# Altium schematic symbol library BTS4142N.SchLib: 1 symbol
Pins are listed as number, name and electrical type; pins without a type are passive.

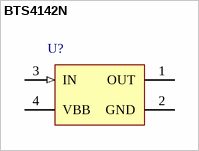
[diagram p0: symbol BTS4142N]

## BTS4142N
designator U?
Smart High-Side Power Switch, 1 Channel, 3 A Load Current, -40 to 150 degC, PG-SOT-223, Reel, Green; Manufacturer: Infineon; PartNumber: BTS4142N; Channels: 1; Green: TRUE; Group: Automotive Qualified; Load Current (typ): 1.4 A; Ptot (max): 1.4 W; Recommended Operating Voltage Max.: 45 V; Recommended Operating Voltage Min.: 12 V; RON @ 25degreesC: 200 mOhm; RON(max) @ 150degreesC: 320 mOhm; toff (max): 150 us; ton (max): 100 us
footprint INF-PG-SOT-223_N (SOT223, 4-Leads, Body 6.5x3.5mm, Pitch 2.3mm, IPC Medium Density)
footprint INF-PG-SOT-223_L (SOT223, 4-Leads, Body 6.5x3.5mm, Pitch 2.3mm, IPC High Density)
footprint INF-PG-SOT-223_M (SOT223, 4-Leads, Body 6.5x3.5mm, Pitch 2.3mm, IPC Low Density)
pins: 1 OUT (power) "Output to the load", 2 GND (power) "Logic ground", 3 IN (in) "Input, activates the power switch in case of logical high signal", 4 VBB (power) "Positive power supply voltage"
